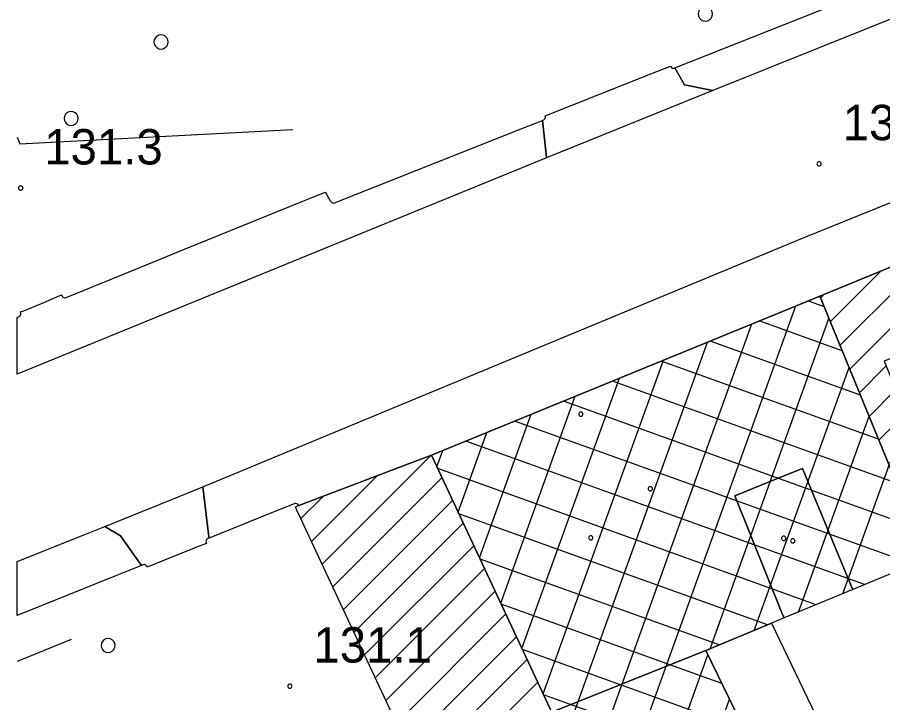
# Model space of a CAD drawing. Extents: x 513373 to 514978, y 5038576 to 5040180.
# Drawn here: x 513373.04 to 513409.71, y 5038852.17 to 5038881.23 of the extents above; entities that cross this region are included whole.
import ezdxf

# ---------------------------------------------------------------- set-up
doc = ezdxf.new("R2010")
doc.units = 0
for name, color, linetype in [('2010300', 7, 'Continuous'), ('3010204', 7, 'Continuous'), ('B1211', 7, 'Continuous'), ('C1131', 7, 'Continuous'), ('C1228', 7, 'Continuous'), ('C21111', 7, 'Continuous'), ('C211113', 7, 'Continuous'), ('C21195', 7, 'Continuous'), ('CAMP_C1228', 7, 'Continuous'), ('CAMP_C21111', 7, 'Continuous'), ('CAMP_C21195', 7, 'Continuous'), ('Default', 7, 'Continuous'), ('F12107', 7, 'Continuous'), ('F12131', 7, 'Continuous'), ('F12132', 7, 'Continuous'), ('G4315', 7, 'Continuous'), ('TOP920', 7, 'Continuous')]:
    doc.layers.add(name, color=color, linetype=linetype)

# ---------------------------------------------------------------- blocks, each defined once
blk = doc.blocks.new('CAMP_09281A84')
at = {"layer": 'CAMP_C1228'}
for p, q in [((-18.35, 6.497), (-10.349, 28.723)), ((-9.148, 28.685), (-9.836, 28.933)), ((-19.252, 8.422), (-12.218, 27.958)), ((-13.987, 14.19), (-8.946, 28.192)), ((-8.382, 26.815), (-11.908, 28.085)), ((-20.153, 10.348), (-14.088, 27.192)), ((-7.617, 24.946), (-13.98, 27.236)), ((-21.054, 12.273), (-15.958, 26.427)), ((-6.851, 23.076), (-16.052, 26.388)), ((-12.112, 14.968), (-8.097, 26.12)), ((-21.955, 14.198), (-17.828, 25.661)), ((-6.086, 21.206), (-18.124, 25.54)), ((-22.856, 16.123), (-19.698, 24.895)), ((-5.32, 19.336), (-20.196, 24.692)), ((-23.757, 18.048), (-21.568, 24.13)), ((-5.378, 17.763), (-22.268, 23.843)), ((-10.238, 15.746), (-7.249, 24.048)), ((-24.659, 19.973), (-23.438, 23.364)), ((-7.436, 16.909), (-24.34, 22.995)), ((-25.56, 21.898), (-25.308, 22.599)), ((-9.493, 16.055), (-25.527, 21.828)), ((-8.364, 16.524), (-6.401, 21.976)), ((-11.55, 15.202), (-24.629, 19.911)), ((-13.606, 14.348), (-23.732, 17.993)), ((-13.486, 12.71), (-22.834, 16.076)), ((-12.553, 10.78), (-21.936, 14.158)), ((-17.449, 4.572), (-14.078, 13.936)), ((-11.62, 8.85), (-21.039, 12.241)), ((-16.548, 2.647), (-13.164, 12.045))]:
    blk.add_line(p, q, dxfattribs=at)
blk = doc.blocks.new('CAMP_DC708B44')
at = {"layer": 'CAMP_C21111'}
for p, q in [((-1.508, -0.498), (4.901, 5.912)), ((-3.439, -1.014), (2.681, 5.106)), ((0.819, 0.415), (5.308, 4.904)), ((-3.85, -0.011), (0.283, 4.122)), ((1.224, -0.595), (5.714, 3.896)), ((-4.26, 0.992), (-2.115, 3.137)), ((2.4, -0.833), (6.12, 2.888)), ((-4.671, 1.996), (-4.514, 2.153)), ((4.775, 0.128), (6.527, 1.88)), ((-3.028, -2.018), (-1.892, -0.882)), ((-2.617, -3.021), (-1.482, -1.886)), ((-2.206, -4.025), (-1.073, -2.891)), ((-1.796, -5.028), (-0.663, -3.895)), ((-1.385, -6.031), (-0.253, -4.9))]:
    blk.add_line(p, q, dxfattribs=at)
blk = doc.blocks.new('CAMP_22BC2A3D')
at = {"layer": 'CAMP_C21195'}
for p, q in [((-9.082, 12.131), (-4.468, 16.745)), ((-9.532, 13.095), (-6.754, 15.873)), ((-8.632, 11.167), (-4.005, 15.794)), ((-9.98, 14.062), (-9.04, 15.001)), ((-8.181, 10.204), (-3.554, 14.831)), ((-7.731, 9.24), (-3.103, 13.868)), ((-7.28, 8.276), (-2.652, 12.904)), ((-6.83, 7.312), (-2.201, 11.941)), ((-6.38, 6.348), (-1.75, 10.978)), ((-5.929, 5.385), (-1.299, 10.015)), ((-5.479, 4.421), (-0.848, 9.051)), ((-5.028, 3.457), (-0.397, 8.088)), ((-4.578, 2.493), (0.054, 7.125))]:
    blk.add_line(p, q, dxfattribs=at)
blk = doc.blocks.new('08020400')
at = {"layer": 'Default'}
for p, q in [((-0.086, 0.028), (-0.09, 0)), ((-0.09, 0), (-0.086, -0.028)), ((-0.073, 0.053), (-0.086, 0.028)), ((-0.053, 0.073), (-0.073, 0.053)), ((-0.028, 0.086), (-0.053, 0.073)), ((0, 0.09), (-0.028, 0.086)), ((0.028, 0.086), (0, 0.09)), ((0.053, 0.073), (0.028, 0.086)), ((0.073, 0.053), (0.053, 0.073)), ((0.086, 0.028), (0.073, 0.053)), ((0.09, 0), (0.086, 0.028)), ((0.086, -0.028), (0.09, 0)), ((-0.086, -0.028), (-0.073, -0.053)), ((-0.073, -0.053), (-0.053, -0.073)), ((-0.053, -0.073), (-0.028, -0.086)), ((-0.028, -0.086), (0, -0.09)), ((0, -0.09), (0.028, -0.086)), ((0.028, -0.086), (0.053, -0.073)), ((0.053, -0.073), (0.073, -0.053)), ((0.073, -0.053), (0.086, -0.028))]:
    blk.add_line(p, q, dxfattribs=at)
blk = doc.blocks.new('NSIMB25')
at = {"layer": 'Default'}
for p, q in [((-0.086, 0.028), (-0.09, 0)), ((-0.09, 0), (-0.086, -0.028)), ((-0.073, 0.053), (-0.086, 0.028)), ((-0.053, 0.073), (-0.073, 0.053)), ((-0.028, 0.086), (-0.053, 0.073)), ((0, 0.09), (-0.028, 0.086)), ((0.028, 0.086), (0, 0.09)), ((0.053, 0.073), (0.028, 0.086)), ((0.073, 0.053), (0.053, 0.073)), ((0.086, 0.028), (0.073, 0.053)), ((0.09, 0), (0.086, 0.028)), ((0.086, -0.028), (0.09, 0)), ((-0.086, -0.028), (-0.073, -0.053)), ((-0.073, -0.053), (-0.053, -0.073)), ((-0.053, -0.073), (-0.028, -0.086)), ((-0.028, -0.086), (0, -0.09)), ((0, -0.09), (0.028, -0.086)), ((0.028, -0.086), (0.053, -0.073)), ((0.053, -0.073), (0.073, -0.053)), ((0.073, -0.053), (0.086, -0.028))]:
    blk.add_line(p, q, dxfattribs=at)
blk = doc.blocks.new('05010100')
at = {"layer": 'Default'}
for p, q in [((-0.143, 0.046), (-0.15, 0)), ((-0.15, 0), (-0.143, -0.046)), ((-0.121, 0.088), (-0.143, 0.046)), ((-0.088, 0.121), (-0.121, 0.088)), ((-0.046, 0.143), (-0.088, 0.121)), ((0, 0.15), (-0.046, 0.143)), ((0.046, 0.143), (0, 0.15)), ((0.088, 0.121), (0.046, 0.143)), ((0.121, 0.088), (0.088, 0.121)), ((0.143, 0.046), (0.121, 0.088)), ((0.15, 0), (0.143, 0.046)), ((0.143, -0.046), (0.15, 0)), ((-0.143, -0.046), (-0.121, -0.088)), ((-0.121, -0.088), (-0.088, -0.121)), ((-0.088, -0.121), (-0.046, -0.143)), ((-0.046, -0.143), (0, -0.15)), ((0, -0.15), (0.046, -0.143)), ((0.046, -0.143), (0.088, -0.121)), ((0.088, -0.121), (0.121, -0.088)), ((0.121, -0.088), (0.143, -0.046))]:
    blk.add_line(p, q, dxfattribs=at)
blk = doc.blocks.new('A$C3704598A')
at = {"layer": '2010300'}
blk.add_lwpolyline([(5.258, -522.145), (4.474, -522.462), (4.195, -522.573), (-0.007, -524.266)], dxfattribs=at)
at = {"layer": '3010204'}
for points in [[(-0.007, -503.994), (0.105, -504.271), (11.671, -503.66)], [(2.278, -525.285), (-0.007, -526.227)]]:
    blk.add_lwpolyline(points, dxfattribs=at)
at = {"layer": 'B1211'}
for points in [[(75.227, -483.607), (51.786, -493.036), (29.459, -502.015), (29.181, -501.959), (28.267, -501.774), (27.86, -501.054), (42.561, -495.215), (42.594, -495.19), (42.613, -495.169), (42.627, -495.142), (42.636, -495.109), (42.637, -495.068), (42.627, -495.029), (45.362, -493.945), (53.631, -490.635), (74.599, -482.242), (75.152, -482.02), (75.977, -481.661), (76.971, -481.229), (77.126, -482.165), (76.541, -483.078)], [(27.86, -501.054), (28.267, -501.774), (29.181, -501.959), (29.459, -502.015), (22.42, -504.868), (22.402, -504.705), (22.242, -503.285), (22.301, -503.259), (22.338, -503.227), (22.36, -503.192), (22.371, -503.16), (22.373, -503.125), (22.366, -503.082), (26.84, -501.306), (27.665, -500.979), (27.695, -501.023), (27.718, -501.041), (27.756, -501.059), (27.797, -501.067), (27.826, -501.065)], [(22.402, -504.705), (22.42, -504.868), (21.42, -505.276), (-0.007, -514.037), (-0.007, -511.629), (0.07, -511.598), (0.105, -511.569), (0.122, -511.545), (0.134, -511.518), (0.141, -511.489), (0.141, -511.455), (0.124, -511.402), (0.267, -511.359), (1.025, -511.037), (1.867, -510.679), (1.874, -510.694), (1.888, -510.727), (1.91, -510.754), (1.936, -510.775), (1.962, -510.788), (1.991, -510.795), (2.025, -510.797), (2.058, -510.791), (5.946, -509.208), (7.014, -508.773), (12.095, -506.703), (12.375, -506.589), (13.037, -506.319), (13.102, -506.429), (13.254, -506.69), (13.274, -506.724), (13.314, -506.763), (13.352, -506.78), (13.391, -506.786), (13.438, -506.78), (21.235, -503.685), (22.242, -503.285)], [(8.118, -520.986), (8.065, -521.01), (8.031, -521.035), (8.01, -521.062), (7.993, -521.102), (7.988, -521.131), (7.991, -521.172), (7.998, -521.19), (8.008, -521.214), (7.7, -521.337), (5.497, -522.218), (5.482, -522.184), (5.46, -522.158), (5.434, -522.137), (5.403, -522.122), (5.37, -522.114), (5.338, -522.117), (5.324, -522.118), (5.287, -522.13), (5.258, -522.145), (4.359, -520.886), (3.705, -520.499), (6.852, -519.225), (7.856, -518.818), (8.099, -520.826)], [(4.359, -520.886), (5.258, -522.145), (4.474, -522.462), (4.195, -522.573), (-0.007, -524.266), (-0.007, -521.982), (2.848, -520.841), (3.705, -520.499)]]:
    blk.add_lwpolyline(points, close=True, dxfattribs=at)
blk.add_lwpolyline([(42.605, -507.199), (33.999, -510.73), (33.037, -511.124), (17.538, -517.47), (16.573, -517.838), (11.921, -519.612), (11.907, -519.586), (11.881, -519.557), (11.842, -519.534), (11.795, -519.521), (11.769, -519.524), (11.747, -519.525), (11.439, -519.649), (10.763, -519.922), (8.118, -520.986), (8.099, -520.826), (7.856, -518.818), (33.194, -508.304), (43.391, -504.176)], dxfattribs=at)
at = {"layer": 'C1131'}
for points in [[(43.63, -506.959), (45.591, -511.823), (40.173, -514.014), (40.114, -513.867), (39.509, -512.36), (38.545, -512.753), (36.731, -513.492), (38.77, -518.49), (37.405, -519.049), (37.343, -518.899), (33.999, -510.73), (42.605, -507.199), (43.431, -506.86), (43.516, -506.836), (43.574, -506.82)], [(37.405, -519.049), (38.555, -521.857), (35.393, -523.169), (35.329, -523.015), (33.27, -518.036), (32.306, -518.425), (30.397, -519.195), (32.422, -524.221), (32.485, -524.376), (31.955, -524.596), (29.168, -525.753), (28.212, -526.137), (22.641, -528.369), (22.575, -528.229), (17.538, -517.47), (33.037, -511.124), (33.999, -510.73), (37.343, -518.899)], [(22.641, -528.369), (23.836, -530.923), (23.913, -531.088), (29.047, -542.054), (29.127, -542.224), (32.095, -548.563), (31.147, -548.968), (26.414, -550.987), (26.35, -550.851), (26.338, -550.826), (12.149, -520.462), (12.026, -520.188), (11.844, -519.807), (11.783, -519.67), (11.921, -519.612), (16.573, -517.838), (17.538, -517.47), (22.575, -528.229)], [(35.393, -523.169), (32.485, -524.376), (32.422, -524.221), (30.397, -519.195), (32.306, -518.425), (33.27, -518.036), (35.329, -523.015)], [(30.394, -528.291), (29.45, -528.699), (23.913, -531.088), (23.836, -530.923), (22.641, -528.369), (28.212, -526.137), (29.168, -525.753)]]:
    blk.add_lwpolyline(points, close=True, dxfattribs=at)
at = {"layer": 'C1228'}
blk.add_lwpolyline([(22.575, -528.229), (17.538, -517.47), (33.037, -511.124), (33.999, -510.73), (37.343, -518.899), (37.405, -519.049), (38.555, -521.857), (35.393, -523.169), (32.485, -524.376), (31.955, -524.596), (29.168, -525.753), (30.394, -528.291)], dxfattribs=at)
at = {"layer": 'C21111'}
blk.add_lwpolyline([(43.63, -506.959), (45.591, -511.823), (40.173, -514.014), (40.114, -513.867), (39.509, -512.36), (38.545, -512.753), (36.731, -513.492), (38.77, -518.49), (37.405, -519.049), (37.343, -518.899), (33.999, -510.73), (42.605, -507.199), (43.431, -506.86), (43.516, -506.836), (43.574, -506.82)], close=True, dxfattribs=at)
at = {"layer": 'C211113'}
blk.add_lwpolyline([(31.955, -524.596), (38.427, -538.079), (38.495, -538.22), (35.731, -539.333), (35.662, -539.192), (30.394, -528.291), (29.168, -525.753)], close=True, dxfattribs=at)
at = {"layer": 'C21195'}
blk.add_lwpolyline([(22.641, -528.369), (23.836, -530.923), (23.913, -531.088), (29.047, -542.054), (29.127, -542.224), (32.095, -548.563), (31.147, -548.968), (26.414, -550.987), (26.35, -550.851), (26.338, -550.826), (12.149, -520.462), (12.026, -520.188), (11.844, -519.807), (11.783, -519.67), (11.921, -519.612), (16.573, -517.838), (17.538, -517.47), (22.575, -528.229)], close=True, dxfattribs=at)
at = {"layer": 'CAMP_C1228'}
blk.add_blockref('CAMP_09281A84', (43.333, -539.869), dxfattribs=at)
at = {"layer": 'CAMP_C21111'}
blk.add_blockref('CAMP_DC708B44', (38.703, -512.806), dxfattribs=at)
at = {"layer": 'CAMP_C21195'}
blk.add_blockref('CAMP_22BC2A3D', (21.991, -534.221), dxfattribs=at)
at = {"layer": 'F12107'}
for p in [(33.968, -505.118), (0.135, -506.147), (11.543, -527.265)]:
    blk.add_blockref('08020400', p, dxfattribs=at)
at = {"layer": 'F12131'}
for p in [(26.816, -518.895), (32.467, -520.998)]:
    blk.add_blockref('NSIMB25', p, dxfattribs=at)
at = {"layer": 'F12132'}
for p in [(23.87, -515.734), (24.291, -520.975), (32.851, -521.108)]:
    blk.add_blockref('NSIMB25', p, dxfattribs=at)
at = {"layer": 'G4315', "xscale": 2, "yscale": 2}
for p in [(29.146, -498.768), (6.085, -499.953), (2.274, -503.197), (3.842, -525.542)]:
    blk.add_blockref('05010100', p, dxfattribs=at)
at = {"layer": 'TOP920'}
for s, p in [('131.2', (34.968, -504.118)), ('131.3', (1.135, -505.147)), ('131.1', (12.543, -526.265))]:
    blk.add_text(s, height=1.5, dxfattribs=at).set_placement(p)

msp = doc.modelspace()

# ---------------------------------------------------------------- block references
at = {"layer": 'Default'}
msp.add_blockref('A$C3704598A', (513373.046, 5039380.14), dxfattribs=at)

doc.saveas('drawing.dxf')
